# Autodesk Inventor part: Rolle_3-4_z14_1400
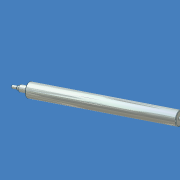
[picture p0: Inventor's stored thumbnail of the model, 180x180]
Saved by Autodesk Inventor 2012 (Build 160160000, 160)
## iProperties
Company: CAD-Verlag
Shininess: 64.0
Length Units: 11269
Angle Units: 11279
Time Units: 11290
Mass Units: 11283
Length Display Precision: 3
Angle Display Precision: 2
Compacted: True
Part Number: Rolle_3-4_z14_1400
Document SubType Name: Modeling
Created: 2004-09
Material: Standard
Designer: Greiling
Manufacturer: Standard
Standards Organization: Custom
Density: 1 g/cm^3
Density: 0.0
Volumn: 0.0
Area: 0.0
PropertySet Name: Model Information
Control State: 0
Master: False
Checked Out: False
Author: Jürgen Kronas
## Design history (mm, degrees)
sketch "Skizze1"
  geometry: L1 (0, 90.805)-(0, -6.985) reference; L2 (0, -6.985)-(0, 90.805) reference; L3 (5, 69.85)-(1395, 69.85); L4 (1400, 64.85)-(1400, 20); L5 (1400, 20)-(1415, 20); L6 (1415, 20)-(1415, 21); L7 (1421, 15)-(1468, 15); L8 (1470, 13)-(1470, 0); L9 (0, 32)-(-28.9, 32); L10 (-40, 32)-(-68.9, 32); L11 (-80, 32)-(-80, 20); L12 (-80, 20)-(-102, 20); L13 (-102, 20)-(-102, 21); L14 (-108, 15)-(-155, 15); L15 (-157, 13)-(-157, 0); L16 (-157, 0)-(1470, 0); L17 (1470, 13)-(1468, 15); L18 (-155, 15)-(-157, 13); L19 (0, 64.85)-(0, 32); L20 (0, 64.85)-(5, 69.85); L21 (1395, 69.85)-(1400, 64.85); L22 (0, 32)-(-80, 32); L23 (10, 0)-(10, 64.85); L24 (10, 64.85)-(1390, 64.85); L25 (1390, 64.85)-(1390, 0); A1 r 6 centre (1421, 21) between (1415, 21) and (1421, 15); A2 r 6 centre (-108, 21) between (-108, 15) and (-102, 21); 6 further points
  constraints: 46 end point, 17 point on line, 6 perpendicular, 5 parallel, 4 point on circle, 4 tangent, 2 centre point, 2 collinear, 1 equal radius
  dimensions: "d1" = 139.7 diameter of L3 L16; "d2" = 40 diameter of L5 L16; "d3" = 30 diameter of L7 L16; "d4" = 30 diameter of L14 L16; "d5" = 40 diameter of L12 L16; "d10" = 80 distance from line of point (0, 69.85) L11; "d11" = 55 distance of point (-102, 15) point (-157, 15); "d12" = 157 distance from line of L15 point (0, 69.85); "d14" = 64 diameter of L9 L16; "d15" = 64 diameter of L10 L16; "d16" = 1400 distance of point (0, 69.85) point (1400, 69.85); "d17" = 70 distance between parallel lines of L4 L8; "d18" = 55 distance of point (1415, 15) point (1470, 15); "d19" = 2 distance of L8.start point (1470, 15); "d20" = 2 distance of L7.end point (1470, 15) (= d19); "d21" = 6 radius of A1; "d22" = 2 distance of L14.end point (-157, 15); "d23" = 2 distance of L15.start point (-157, 15) (= d22); "d32" = 5 distance of L19.start point (0, 69.85); "d33" = 5 distance of L3.start point (0, 69.85) (= d32); "d34" = 5 distance of L3.end point (1400, 69.85) (= d32); "d35" = 5 distance of L4.start point (1400, 69.85) (= d34); "d37" = 10 distance between parallel lines of L4 L25; "d38" = 5 distance between parallel lines of L3 L24; "d39" = 10 distance between parallel lines of L23 L1
revolve "Drehung1" sketch "Skizze1" stored, may be unused: angle "d36" = 90 deg
node "Volumenkörper1"
node "Volumenkörpern"
node "Oberflächenkörpern"
